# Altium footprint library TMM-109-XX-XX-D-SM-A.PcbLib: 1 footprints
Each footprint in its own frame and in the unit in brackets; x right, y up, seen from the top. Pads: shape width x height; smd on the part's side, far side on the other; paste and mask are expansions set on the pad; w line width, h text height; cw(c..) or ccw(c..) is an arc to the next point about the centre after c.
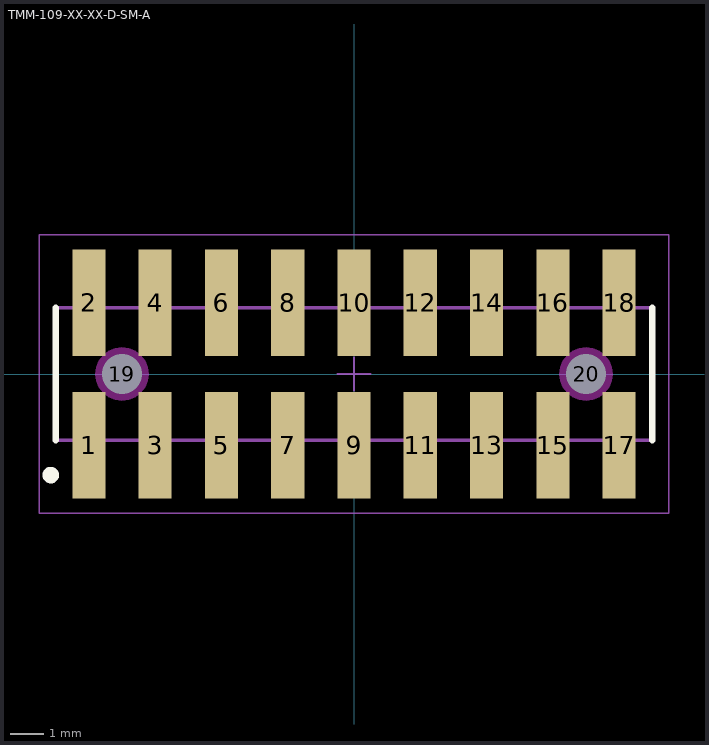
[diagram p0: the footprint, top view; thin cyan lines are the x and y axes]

## TMM-109-XX-XX-D-SM-A [mm] "2.00mm pitch, 18 pin, terminal strip; double row, w/alignment pins, SMT"
height 2.77
pads (20):
  rect 1x3.2 smd mask+0: 1(-8,-2.15) 2(-8,2.15) 3(-6,-2.15) 4(-6,2.15) 5(-4,-2.15) 6(-4,2.15) 7(-2,-2.15) 8(-2,2.15) 9(0,-2.15) 10(0,2.15) 11(2,-2.15) 12(2,2.15) 13(4,-2.15) 14(4,2.15) 15(6,-2.15) 16(6,2.15) 17(8,-2.15) 18(8,2.15)
  round 1 hole 1.2 unplated mask+0: 19(-7,0) 20(7,0)
Top Overlay:
  circle w0.25: c-9.15,-3.05 r0.125
  lines w0.2: -9,-2 -9,2 ; 9,-2 9,2
Keep-Out Layer:
  pour cut-out: -6.193,0 -6.221,0.209 -6.301,0.403 -6.429,0.571 -6.597,0.699 -6.791,0.779 -7,0.807 -7.209,0.779 -7.403,0.699 -7.571,0.571 -7.699,0.403 -7.779,0.209 -7.807,0 -7.779,-0.209 -7.699,-0.403 -7.571,-0.571 -7.403,-0.699 -7.209,-0.779 -7,-0.807 -6.791,-0.779 -6.597,-0.699 -6.429,-0.571 -6.301,-0.403 -6.221,-0.209
  pour cut-out: 7.807,0 7.779,0.209 7.699,0.403 7.571,0.571 7.403,0.699 7.209,0.779 7,0.807 6.791,0.779 6.597,0.699 6.429,0.571 6.301,0.403 6.221,0.209 6.193,0 6.221,-0.209 6.301,-0.403 6.429,-0.571 6.597,-0.699 6.791,-0.779 7,-0.807 7.209,-0.779 7.403,-0.699 7.571,-0.571 7.699,-0.403 7.779,-0.209
Mechanical 12:
  lines w0.001: -9,-2 9,-2 9,2 -9,2 -9,-2
Mechanical 13:
  lines w0.1: -9,-2 9,-2 9,2 -9,2 -9,-2
  text ".Designator" at 0,-0.127 h1.52
Mechanical 15:
  lines w0.05: -0.5,0 0.5,0 ; 0,-0.5 0,0.5 ; -9.5,-4.2 9.5,-4.2 9.5,4.2 -9.5,4.2 -9.5,-4.2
